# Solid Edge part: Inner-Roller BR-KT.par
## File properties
Last saved by: nakano
Revision: 73
Accuracy: 0.990
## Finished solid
Body 1: solid body, 7 faces, 6 edges, 0 vertices.
  Faces by surface: cylinder 2, plane 2, torus 2, sphere 1
  Edges by curve: circle 6
Bounding box of the edges (mm; curved faces can reach further): 9.525 x 1.575 x 1.575, from (-4.7625, -0.7874, -0.7874) to (4.7625, 0.7874, 0.7874).
Cylindrical faces by radius (mm): R0.7874 x2
Toroidal faces (ring radius, tube radius in mm): R0.6604 r0.127 x2
Spherical faces by radius (mm): R2.9972 x1
Planar faces by outward normal: +x 1, -x 1
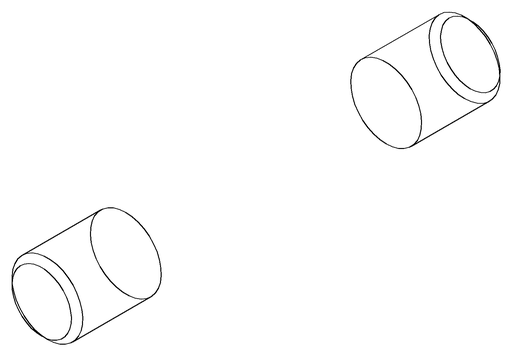
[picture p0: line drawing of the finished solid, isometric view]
